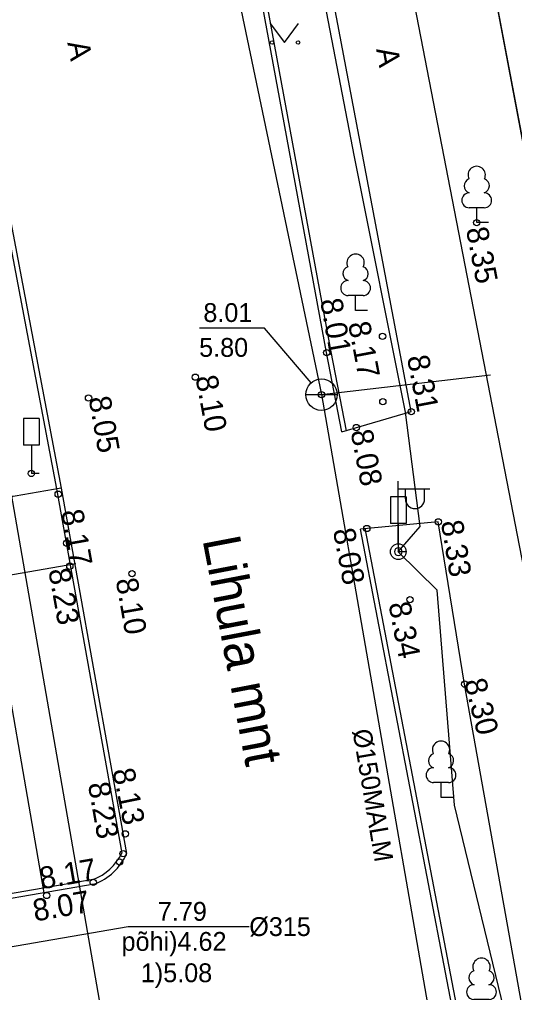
# Model space of a CAD drawing. Extents: x 473307 to 473719, y 6532843 to 6533381.
# Drawn here: x 473612.32 to 473628.1, y 6533222.19 to 6533253.2 of the extents above; entities that cross this region are included whole.
import ezdxf

# ---------------------------------------------------------------- set-up
doc = ezdxf.new("R2010")
doc.units = 0
for name, color, linetype in [('Default', 7, 'Continuous'), ('HALJASTUS', 7, 'Continuous'), ('KORGUS', 7, 'Continuous'), ('LIIKLUS', 7, 'Continuous'), ('MPKAABEL', 7, 'Continuous'), ('PIIR', 7, 'Continuous'), ('POST', 7, 'Continuous'), ('PUU', 7, 'Continuous'), ('SITRASS', 7, 'Continuous'), ('SKKAEV_NR', 7, 'Continuous'), ('TEE', 7, 'Continuous'), ('VKAEV', 7, 'Continuous'), ('VKAEV_NR', 7, 'Continuous'), ('VTRASS', 7, 'Continuous'), ('VTRASS_TEKST', 7, 'Continuous')]:
    doc.layers.add(name, color=color, linetype=linetype)

# ---------------------------------------------------------------- blocks, each defined once
blk = doc.blocks.new('LEHTP1')
at = {"layer": 'Default'}
for p, q in [((0.48, 0.95), (-0.48, 0.95)), ((0, 0), (0, 0.95)), ((0.76, 0), (0, 0))]:
    blk.add_line(p, q, dxfattribs=at)
for centre, radius, start, end in [((0, 3.04), 0.554, 332.5799, 207.4201), ((-0.34, 2.345), 0.465, 109.02174, 253.14154), ((0.34, 2.345), 0.465, 286.85082, 70.98591), ((-0.475, 1.425), 0.475, 90.0016, 269.3953), ((0.475, 1.425), 0.475, 270.6047, 89.9984)]:
    blk.add_arc(centre, radius, start, end, dxfattribs=at)
blk = doc.blocks.new('LIIKLM')
at = {"layer": 'Default'}
for points in [[(-0.5, 3.5), (-0.5, 1.8)], [(0.5, 3.5), (-0.5, 3.5)], [(0.5, 3.5), (0.5, 1.8)], [(0.5, 1.8), (-0.5, 1.8)], [(0, 1.8), (0, 0)], [(0.5, 0), (0, 0)]]:
    blk.add_lwpolyline(points, dxfattribs=at)
blk = doc.blocks.new('VEKAEV')
at = {"layer": 'Default'}
blk.add_line((-1, 0), (1, 0), dxfattribs=at)
blk.add_circle((0, 0), 1, dxfattribs=at)
blk = doc.blocks.new('MURU')
at = {"layer": 'Default'}
for p, q in [((-0.927, 1.213), (0, 0)), ((0, 0), (0.891, 1.213))]:
    blk.add_line(p, q, dxfattribs=at)
for centre in [(-0.802, 0), (0.856, 0)]:
    blk.add_circle(centre, 0.11, dxfattribs=at)
blk = doc.blocks.new('MEPOST')
at = {"layer": 'Default'}
blk.add_circle((0, 0), 0.5, dxfattribs=at)
for start, end in [(0, 180), (180, 0)]:
    blk.add_arc((0, 0), 0.25, start, end, dxfattribs=at)
blk = doc.blocks.new('VAPOST')
at = {"layer": 'Default'}
for p, q in [((0, 0.5), (0, 4.5)), ((0, 4), (2, 4)), ((0.453, 3.358), (0.453, 4)), ((1.679, 3.358), (1.679, 4))]:
    blk.add_line(p, q, dxfattribs=at)
blk.add_arc((1.066, 3.358), 0.613, 180, 0, dxfattribs=at)

msp = doc.modelspace()

# ---------------------------------------------------------------- linework, layer by layer
at = {"layer": 'KORGUS'}
for centre in [(473626.894, 6533246.724), (473623.893, 6533243.102), (473622.111, 6533242.583), (473617.928, 6533241.8), (473621.946, 6533241.242), (473621.946, 6533241.242), (473621.946, 6533241.242), (473621.946, 6533241.242), (473621.946, 6533241.242), (473614.523, 6533241.136), (473623.903, 6533241.018), (473624.808, 6533240.702), (473623.058, 6533240.194), (473612.7, 6533238.731), (473613.556, 6533238.071), (473625.67, 6533237.189), (473623.392, 6533236.976), (473613.83, 6533236.508), (473613.927, 6533235.775), (473615.908, 6533235.534), (473624.766, 6533234.708), (473626.508, 6533232.017), (473615.695, 6533227.244), (473615.625, 6533226.616), (473615.515, 6533226.351), (473614.672, 6533225.702), (473613.185, 6533225.28)]:
    msp.add_circle(centre, 0.1, dxfattribs=at)
at = {"layer": 'MPKAABEL'}
for points in [[(473636.059, 6533169.782), (473634.239, 6533181.673), (473632.606, 6533189.833), (473631.267, 6533197.327), (473629.932, 6533205.197), (473627.365, 6533217.651), (473628.02, 6533220.588), (473626.187, 6533228.162), (473625.63, 6533235.006), (473624.395, 6533236.238), (473625.088, 6533237.039), (473624.62, 6533240.685), (473623.001, 6533248.826), (473621.554, 6533256.337), (473620.191, 6533259.447), (473620.669, 6533261.927), (473620.008, 6533272.193), (473619.024, 6533281.587), (473618.831, 6533288.933), (473618.813, 6533289.306)], [(473624.395, 6533236.238), (473625.088, 6533237.039), (473624.62, 6533240.685), (473623.001, 6533248.826), (473621.554, 6533256.337), (473620.191, 6533259.447)], [(473627.365, 6533217.651), (473628.02, 6533220.588), (473626.187, 6533228.162), (473625.63, 6533235.006), (473624.395, 6533236.238)]]:
    msp.add_lwpolyline(points, dxfattribs=at)
at = {"layer": 'PIIR'}
msp.add_lwpolyline([(473609.342, 6533380.885), (473610.48, 6533371.09), (473616.72, 6533301.5), (473621.56, 6533285.32), (473637.37, 6533201.6), (473653.19, 6533109.36), (473652.55, 6533109.39), (473658.35, 6533068.44), (473658.1, 6533064.14), (473666.14, 6533015.71), (473666.15, 6533015.71), (473680.29, 6532930.36), (473685.16, 6532910.71), (473685.75, 6532908.33), (473689.51, 6532885.44), (473695.16, 6532852.24), (473696.267, 6532845.502)], dxfattribs=at)
msp.add_lwpolyline([(473621.56, 6533285.32), (473669.64, 6533273.05), (473669.6, 6533193.05), (473637.37, 6533201.6)], close=True, dxfattribs=at)
at = {"layer": 'SITRASS'}
msp.add_lwpolyline([(473619.598, 6533194.755), (473606.651, 6533269.171)], dxfattribs=at)
at = {"layer": 'SKKAEV_NR'}
msp.add_lwpolyline([(473605.62, 6533222.541), (473615.79, 6533224.289), (473619.645, 6533224.289)], dxfattribs=at)
at = {"layer": 'TEE'}
for points in [[(473606.081, 6533277.468), (473606.665, 6533274.345), (473613.506, 6533238.237), (473615.579, 6533226.633)], [(473606.226, 6533277.506), (473606.812, 6533274.373), (473613.654, 6533238.264), (473613.654, 6533238.264), (473615.735, 6533226.614)], [(473636.262, 6533193.178), (473634.427, 6533200.58), (473629.069, 6533232.269), (473622.112, 6533268.179), (473620.414, 6533277.349)], [(473622.594, 6533240.06), (473624.808, 6533240.702), (473619.671, 6533267.817), (473617.77, 6533276.829)], [(473613.654, 6533238.264), (473610.95, 6533237.796), (473604.734, 6533274.019), (473606.812, 6533274.373)], [(473622.594, 6533240.06), (473622.111, 6533242.583), (473616.323, 6533273.948)], [(473622.742, 6533240.088), (473622.258, 6533242.611), (473616.471, 6533273.975)], [(473633.632, 6533192.148), (473626.508, 6533232.017), (473625.67, 6533237.189), (473623.189, 6533236.957)], [(473631.487, 6533191.503), (473631.245, 6533193.006), (473626.98, 6533217.172), (473623.189, 6533236.957)], [(473631.635, 6533191.527), (473631.393, 6533193.031), (473627.128, 6533217.199), (473623.336, 6533236.985)], [(473614.114, 6533235.854), (473611.354, 6533235.374), (473613.096, 6533225.365)], [(473614.666, 6533225.79), (473609.751, 6533224.935), (473605.918, 6533224.253)], [(473614.705, 6533225.644), (473609.777, 6533224.788), (473605.907, 6533224.098)]]:
    msp.add_lwpolyline(points, dxfattribs=at)
for radius, start, end in [(1.657, 290.6783, 334.7552), (1.807, 290.2183, 336.3018)]:
    msp.add_arc((473614.081, 6533227.34), radius, start, end, dxfattribs=at)
at = {"layer": 'VKAEV_NR'}
msp.add_lwpolyline([(473621.621, 6533241.622), (473620.132, 6533243.358), (473618.061, 6533243.358)], dxfattribs=at)
at = {"layer": 'VTRASS'}
for points in [[(473610.467, 6533298.54), (473612.816, 6533284.928), (473621.946, 6533241.242), (473627.014, 6533212.114), (473627.084, 6533211.254), (473634.761, 6533160.18), (473647.035, 6533084.422), (473650.297, 6533065.838)], [(473621.946, 6533241.242), (473627.337, 6533241.878)]]:
    msp.add_lwpolyline(points, dxfattribs=at)

# ---------------------------------------------------------------- block references
at = {"layer": 'HALJASTUS', "xscale": 0.5, "yscale": 0.5}
msp.add_blockref('MURU', (473620.771, 6533252.467), dxfattribs=at)
at = {"layer": 'LIIKLUS', "xscale": 0.5, "yscale": 0.5}
for p in [(473612.7, 6533238.731), (473624.395, 6533236.238)]:
    msp.add_blockref('LIIKLM', p, dxfattribs=at)
at = {"layer": 'POST', "xscale": 0.5, "yscale": 0.5}
for name in ['VAPOST', 'MEPOST']:
    msp.add_blockref(name, (473624.395, 6533236.238), dxfattribs=at)
at = {"layer": 'PUU', "xscale": 0.5, "yscale": 0.5}
for p in [(473626.894, 6533246.724), (473623.034, 6533243.926), (473625.757, 6533228.403), (473627.047, 6533221.487)]:
    msp.add_blockref('LEHTP1', p, dxfattribs=at)
at = {"layer": 'VKAEV', "xscale": 0.5, "yscale": 0.5}
msp.add_blockref('VEKAEV', (473621.946, 6533241.242), dxfattribs=at)

# ---------------------------------------------------------------- texts
at = {"layer": 'KORGUS'}
for s, rotation, p in [('8.35', 280.867, (473626.548, 6533246.523)), ('8.01', 280, (473621.902, 6533244.255)), ('8.17', 280.7284, (473622.792, 6533243.511)), ('8.31', 280.7284, (473624.668, 6533242.441)), ('8.10', 280.459, (473617.928, 6533241.8)), ('8.05', 280, (473614.523, 6533241.136)), ('8.08', 280.847, (473622.872, 6533240.07)), ('8.17', 280.1294, (473613.648, 6533237.525)), ('8.08', 280.847, (473622.307, 6533236.924)), ('8.33', 279.1986, (473625.752, 6533237.189)), ('8.23', 280.1294, (473613.238, 6533235.652)), ('8.10', 279.9524, (473615.385, 6533235.344)), ('8.34', 280.847, (473624.079, 6533234.576)), ('8.30', 283.8459, (473626.49, 6533232.11)), ('8.13', 281.5546, (473615.281, 6533229.269)), ('8.23', 279.9524, (473614.5, 6533228.838)), ('8.17', 9.8626, (473613.021, 6533225.474)), ('8.07', 9.8626, (473612.813, 6533224.45))]:
    msp.add_text(s, height=0.7, rotation=rotation, dxfattribs=at).set_placement(p)
at = {"layer": 'SKKAEV_NR'}
for s, p in [('7.79', (473616.732, 6533224.475)), ('%%c315', (473619.645, 6533223.989)), ('põhi)4.62', (473615.575, 6533223.517)), ('1)5.08', (473616.189, 6533222.517))]:
    msp.add_text(s, height=0.6, dxfattribs=at).set_placement(p)
at = {"layer": 'TEE'}
for s, height, rotation, p in [('A', 0.7, 280.3995, (473613.845, 6533252.461)), ('A', 0.7, 279.9555, (473623.686, 6533252.254)), ('Lihula mnt', 1.2, 280.8393, (473618.152, 6533236.625))]:
    msp.add_text(s, height=height, rotation=rotation, dxfattribs=at).set_placement(p)
at = {"layer": 'VKAEV_NR'}
for s, p in [('8.01', (473618.182, 6533243.558)), ('5.80', (473618.048, 6533242.448))]:
    msp.add_text(s, height=0.6, dxfattribs=at).set_placement(p)
at = {"layer": 'VTRASS_TEKST'}
msp.add_text('%%c150MALM', height=0.6, rotation=279.6597, dxfattribs=at).set_placement((473622.932, 6533230.536))

doc.saveas('drawing.dxf')
